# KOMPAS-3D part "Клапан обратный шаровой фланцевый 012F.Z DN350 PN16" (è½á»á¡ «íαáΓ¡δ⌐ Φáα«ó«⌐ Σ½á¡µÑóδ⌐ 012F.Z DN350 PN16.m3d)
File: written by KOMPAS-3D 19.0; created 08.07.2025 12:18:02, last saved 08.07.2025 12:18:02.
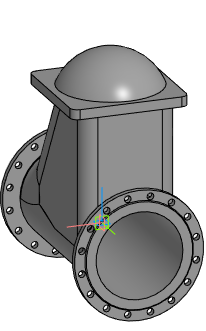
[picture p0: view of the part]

Document properties: Полное имя файла: E:\Dendor Работа Сачек\3D для проектировщиков\5.3 Тип 012F, 012F.Z Клапан обратный шаровой фланцевый\stp_Клапан обратный шаровой фланцевый 012F.Z PN10_16\Клапан обратный шаровой фланцевый 012F.Z DN350 PN16.m3d

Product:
- Part/product: Клапан обратный шаровой фланцевый 012F.Z DN350 PN16

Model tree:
1. Операция без истории:1  (labels: Клапан обратный шаровой фланцевый 012F.Z DN350 PN16)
